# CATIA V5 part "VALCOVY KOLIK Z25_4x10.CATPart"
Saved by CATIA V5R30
Part number: VALCOVY KOLIK Z25/4x10
Bounding box of the stored display mesh (mm): x -10 to -0.009, y -2 to 2, z -2 to 2
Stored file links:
  C:\Users\ondra\Desktop\PŘÍLOHA P III\CATIA\VALCOVY KOLIK Z25_4x10.CATPart
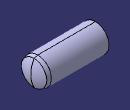
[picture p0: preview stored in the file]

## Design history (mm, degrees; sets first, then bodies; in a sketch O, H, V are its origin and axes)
Set1
  DatumSurface1 to DatumSurface8 "Z25/4x10"
  Join1: Elements (DatumSurface1; DatumSurface2; DatumSurface3; DatumSurface4; DatumSurface5; DatumSurface6; DatumSurface7; DatumSurface8)
Body1 (main body)
  CloseSurface1: CloseElement Join1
